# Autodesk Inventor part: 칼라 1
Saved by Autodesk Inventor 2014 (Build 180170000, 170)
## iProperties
Created: 2026-04
Part Number: 칼라 1
Material: 강철, 연강
Document SubType Name: Modeling
Designer: dg
Density: 7.86 g/cm^3
Appearance: 강철
Author: jhkim
Creation Date: 2026-03-27
Sending System: Autodesk Inventor 2026
Preprocessor: ST-DEVELOPER v20.1
Author: dg
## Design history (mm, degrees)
node "칼라 11"
node "솔리드1"
node "기준1"
